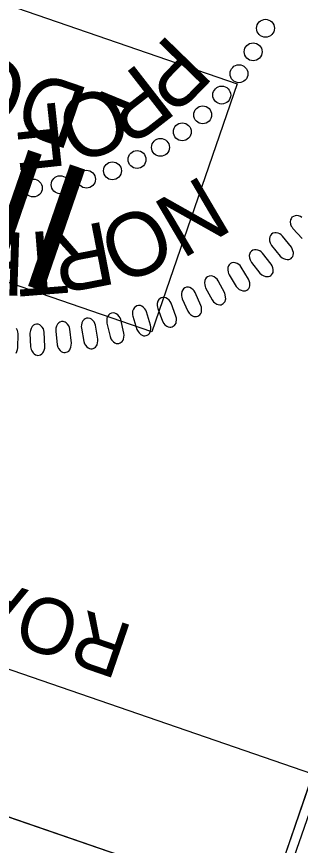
# Model space of a CAD drawing. Extents: x 479650 to 481768, y 492454 to 494037.
# Drawn here: x 479848.6 to 479874, y 492981.7 to 493055.9 of the extents above; entities that cross this region are included whole.
import ezdxf

# ---------------------------------------------------------------- set-up
doc = ezdxf.new("R2010")
doc.units = 0
for name, color, linetype in [('Sheet Clip Boundary CELL', 7, 'Continuous'), ('Sheet PE Seal Cell', 7, 'Continuous'), ('Sheet Plan CELL', 7, 'Continuous'), ('Sheet Sticker Incomplete CELL', 7, 'Continuous')]:
    doc.layers.add(name, color=color, linetype=linetype)

msp = doc.modelspace()

# ---------------------------------------------------------------- linework, layer by layer
at = {"layer": 'Sheet Clip Boundary CELL'}
msp.add_lwpolyline([(480865.415, 492806.897), (480865.415, 492806.897), (481216.518, 493064.432), (481296.644, 493123.205), (481433.971, 493521.819), (480177.877, 493954.834), (480146.865, 493864.823), (480073.721, 493890.25), (479959.678, 493732.811), (479819.951, 493331.117), (479813.597, 493153.331), (479920.245, 493116.586), (479863.719, 492952.486), (480677.398, 492672.068), (480745.444, 492725.051)], close=True, dxfattribs=at)
at = {"layer": 'Sheet PE Seal Cell'}
for points in [[(479874.125, 493037.924), (479873.998, 493037.997), (479873.825, 493038.055), (479873.648, 493038.084), (479873.522, 493038.077), (479873.365, 493038.016), (479873.241, 493037.93), (479873.158, 493037.801), (479873.113, 493037.694), (479873.086, 493037.534), (479873.111, 493037.329), (479873.182, 493037.15), (479873.247, 493037.034), (479873.323, 493036.928), (479874.146, 493036.019)], [(479848.528, 493025.754), (479848.598, 493025.902), (479848.661, 493026.081), (479848.686, 493026.24), (479848.716, 493027.496), (479848.697, 493027.666), (479848.654, 493027.806), (479848.568, 493027.968)]]:
    msp.add_lwpolyline(points, dxfattribs=at)
for points in [[(479871.423, 493035.415), (479872.188, 493034.456), (479872.353, 493034.308), (479872.481, 493034.231), (479872.675, 493034.168), (479872.819, 493034.143), (479872.957, 493034.151), (479873.063, 493034.185), (479873.164, 493034.24), (479873.239, 493034.325), (479873.313, 493034.423), (479873.358, 493034.535), (479873.378, 493034.678), (479873.375, 493034.778), (479873.334, 493034.937), (479873.269, 493035.114), (479873.187, 493035.253), (479872.409, 493036.24), (479872.286, 493036.359), (479872.164, 493036.44), (479871.994, 493036.509), (479871.82, 493036.548), (479871.694, 493036.55), (479871.534, 493036.499), (479871.405, 493036.421), (479871.313, 493036.297), (479871.262, 493036.193), (479871.224, 493036.035), (479871.237, 493035.829), (479871.296, 493035.646), (479871.354, 493035.526)], [(479869.616, 493033.898), (479870.373, 493032.933), (479870.538, 493032.784), (479870.665, 493032.706), (479870.858, 493032.642), (479871.002, 493032.616), (479871.139, 493032.622), (479871.246, 493032.655), (479871.347, 493032.709), (479871.423, 493032.794), (479871.498, 493032.892), (479871.544, 493033.003), (479871.565, 493033.146), (479871.563, 493033.246), (479871.523, 493033.405), (479871.459, 493033.584), (479871.379, 493033.722), (479870.609, 493034.716), (479870.486, 493034.835), (479870.365, 493034.917), (479870.196, 493034.988), (479870.022, 493035.028), (479869.896, 493035.03), (479869.735, 493034.981), (479869.606, 493034.904), (479869.512, 493034.781), (479869.461, 493034.677), (479869.422, 493034.52), (479869.433, 493034.313), (479869.491, 493034.13), (479869.548, 493034.01)], [(479867.62, 493032.786), (479868.258, 493031.738), (479868.405, 493031.571), (479868.522, 493031.478), (479868.706, 493031.392), (479868.846, 493031.349), (479868.983, 493031.339), (479869.093, 493031.36), (479869.199, 493031.401), (479869.285, 493031.476), (479869.371, 493031.565), (479869.43, 493031.669), (479869.467, 493031.809), (479869.477, 493031.909), (479869.456, 493032.071), (479869.414, 493032.256), (479869.35, 493032.404), (479868.702, 493033.48), (479868.595, 493033.614), (479868.484, 493033.709), (479868.324, 493033.799), (479868.156, 493033.86), (479868.031, 493033.877), (479867.866, 493033.846), (479867.728, 493033.786), (479867.621, 493033.674), (479867.558, 493033.577), (479867.501, 493033.426), (479867.487, 493033.219), (479867.523, 493033.03), (479867.565, 493032.904)], [(479865.512, 493031.622), (479866.084, 493030.537), (479866.219, 493030.36), (479866.33, 493030.261), (479866.509, 493030.162), (479866.646, 493030.111), (479866.782, 493030.092), (479866.893, 493030.106), (479867.002, 493030.141), (479867.092, 493030.21), (479867.184, 493030.293), (479867.248, 493030.394), (479867.295, 493030.531), (479867.31, 493030.63), (479867.301, 493030.794), (479867.27, 493030.98), (479867.216, 493031.132), (479866.636, 493032.247), (479866.537, 493032.387), (479866.433, 493032.49), (479866.279, 493032.589), (479866.115, 493032.66), (479865.992, 493032.686), (479865.825, 493032.665), (479865.683, 493032.613), (479865.57, 493032.508), (479865.5, 493032.416), (479865.434, 493032.268), (479865.407, 493032.062), (479865.431, 493031.872), (479865.465, 493031.744)], [(479863.417, 493030.642), (479863.919, 493029.523), (479864.043, 493029.337), (479864.148, 493029.231), (479864.32, 493029.123), (479864.452, 493029.062), (479864.588, 493029.035), (479864.7, 493029.042), (479864.81, 493029.07), (479864.904, 493029.134), (479865.001, 493029.211), (479865.072, 493029.307), (479865.127, 493029.442), (479865.149, 493029.539), (479865.149, 493029.703), (479865.13, 493029.891), (479865.085, 493030.045), (479864.577, 493031.195), (479864.488, 493031.341), (479864.389, 493031.449), (479864.242, 493031.558), (479864.082, 493031.641), (479863.961, 493031.674), (479863.794, 493031.664), (479863.649, 493031.62), (479863.529, 493031.522), (479863.454, 493031.434), (479863.378, 493031.292), (479863.339, 493031.088), (479863.351, 493030.896), (479863.377, 493030.766)], [(479861.225, 493029.769), (479861.656, 493028.62), (479861.768, 493028.429), (479861.866, 493028.316), (479862.031, 493028.197), (479862.16, 493028.128), (479862.293, 493028.092), (479862.405, 493028.092), (479862.517, 493028.113), (479862.616, 493028.171), (479862.716, 493028.241), (479862.794, 493028.333), (479862.857, 493028.464), (479862.885, 493028.56), (479862.895, 493028.724), (479862.888, 493028.912), (479862.853, 493029.07), (479862.419, 493030.249), (479862.338, 493030.4), (479862.247, 493030.515), (479862.107, 493030.632), (479861.953, 493030.724), (479861.834, 493030.765), (479861.666, 493030.765), (479861.519, 493030.731), (479861.393, 493030.641), (479861.312, 493030.558), (479861.228, 493030.42), (479861.176, 493030.219), (479861.176, 493030.028), (479861.194, 493029.896)], [(479858.995, 493029.068), (479859.353, 493027.895), (479859.453, 493027.696), (479859.543, 493027.578), (479859.7, 493027.448), (479859.825, 493027.372), (479859.955, 493027.328), (479860.068, 493027.32), (479860.18, 493027.334), (479860.282, 493027.386), (479860.387, 493027.449), (479860.47, 493027.537), (479860.541, 493027.663), (479860.575, 493027.757), (479860.596, 493027.92), (479860.601, 493028.109), (479860.575, 493028.268), (479860.216, 493029.472), (479860.144, 493029.628), (479860.061, 493029.749), (479859.929, 493029.875), (479859.781, 493029.975), (479859.665, 493030.024), (479859.497, 493030.035), (479859.348, 493030.01), (479859.217, 493029.928), (479859.132, 493029.85), (479859.039, 493029.718), (479858.974, 493029.521), (479858.962, 493029.329), (479858.971, 493029.196)], [(479854.383, 493028.017), (479854.591, 493026.808), (479854.665, 493026.597), (479854.74, 493026.469), (479854.879, 493026.321), (479854.993, 493026.229), (479855.117, 493026.17), (479855.227, 493026.148), (479855.341, 493026.148), (479855.448, 493026.186), (479855.561, 493026.236), (479855.654, 493026.313), (479855.74, 493026.429), (479855.786, 493026.518), (479855.827, 493026.676), (479855.855, 493026.864), (479855.85, 493027.025), (479855.644, 493028.264), (479855.594, 493028.427), (479855.525, 493028.557), (479855.411, 493028.699), (479855.276, 493028.818), (479855.167, 493028.88), (479855.002, 493028.913), (479854.851, 493028.907), (479854.711, 493028.842), (479854.616, 493028.775), (479854.507, 493028.655), (479854.419, 493028.468), (479854.382, 493028.28), (479854.375, 493028.147)], [(479856.662, 493028.439), (479856.946, 493027.246), (479857.033, 493027.041), (479857.116, 493026.917), (479857.264, 493026.778), (479857.384, 493026.694), (479857.511, 493026.642), (479857.622, 493026.628), (479857.736, 493026.634), (479857.841, 493026.679), (479857.95, 493026.736), (479858.038, 493026.818), (479858.117, 493026.94), (479858.157, 493027.031), (479858.188, 493027.192), (479858.204, 493027.381), (479858.189, 493027.542), (479857.906, 493028.766), (479857.845, 493028.925), (479857.769, 493029.051), (479857.644, 493029.185), (479857.503, 493029.295), (479857.391, 493029.351), (479857.224, 493029.372), (479857.074, 493029.357), (479856.937, 493029.284), (479856.847, 493029.211), (479856.746, 493029.085), (479856.67, 493028.892), (479856.646, 493028.701), (479856.646, 493028.569)], [(479849.777, 493027.545), (479849.832, 493026.319), (479849.879, 493026.101), (479849.937, 493025.964), (479850.057, 493025.8), (479850.159, 493025.694), (479850.275, 493025.62), (479850.381, 493025.585), (479850.494, 493025.57), (479850.605, 493025.595), (479850.724, 493025.63), (479850.825, 493025.695), (479850.926, 493025.799), (479850.981, 493025.881), (479851.042, 493026.034), (479851.094, 493026.216), (479851.109, 493026.376), (479851.06, 493027.632), (479851.03, 493027.8), (479850.979, 493027.938), (479850.882, 493028.093), (479850.764, 493028.227), (479850.664, 493028.303), (479850.504, 493028.356), (479850.353, 493028.369), (479850.206, 493028.322), (479850.104, 493028.268), (479849.981, 493028.162), (479849.869, 493027.988), (479849.81, 493027.805), (479849.786, 493027.675)], [(479852.083, 493027.737), (479852.214, 493026.517), (479852.275, 493026.303), (479852.343, 493026.17), (479852.472, 493026.013), (479852.581, 493025.915), (479852.701, 493025.847), (479852.809, 493025.819), (479852.922, 493025.811), (479853.032, 493025.843), (479853.147, 493025.885), (479853.245, 493025.956), (479853.339, 493026.067), (479853.389, 493026.152), (479853.44, 493026.308), (479853.48, 493026.493), (479853.486, 493026.654), (479853.357, 493027.904), (479853.317, 493028.071), (479853.257, 493028.205), (479853.151, 493028.353), (479853.024, 493028.481), (479852.92, 493028.549), (479852.757, 493028.592), (479852.606, 493028.596), (479852.462, 493028.54), (479852.363, 493028.479), (479852.248, 493028.366), (479852.147, 493028.185), (479852.099, 493027.999), (479852.083, 493027.867)]]:
    msp.add_lwpolyline(points, close=True, dxfattribs=at)
for centre in [(479870.87, 493054.858), (479869.765, 493052.753), (479868.498, 493050.788), (479866.954, 493048.877), (479865.248, 493047.105), (479863.419, 493045.587), (479861.465, 493044.196), (479859.364, 493043.109), (479857.162, 493042.098), (479852.477, 493040.848), (479854.837, 493041.341), (479850.076, 493040.554)]:
    msp.add_circle(centre, 0.801, dxfattribs=at)
at = {"layer": 'Sheet Plan CELL'}
for q in [(479681.911, 493041.391), (479681.911, 493041.391), (479875.114, 492988.059)]:
    msp.add_line((479871.047, 492976.253), q, dxfattribs=at)
for points in [[(481433.971, 493521.819), (481091.969, 492529.104), (479862.874, 492952.534), (479911.745, 493094.415), (479722.622, 493159.589), (480015.773, 494010.441)], [(479875.114, 492988.059), (479780.521, 493020.65), (479817.172, 493127.026), (479911.745, 493094.415)], [(479862.874, 492952.534), (479673.716, 493017.719), (479681.911, 493041.391), (479871.047, 492976.253)]]:
    msp.add_lwpolyline(points, close=True, dxfattribs=at)
at = {"layer": 'Sheet Sticker Incomplete CELL'}
msp.add_lwpolyline([(479868.336, 493049.89), (479860.681, 493027.672), (479721.698, 493075.556), (479729.353, 493097.774)], close=True, dxfattribs=at)

# ---------------------------------------------------------------- texts
at = {"layer": 'Sheet PE Seal Cell'}
for s, rotation, p in [('P', 225.79665, (479862.285, 493054.494)), ('R', 217.85685, (479859.595, 493051.865)), ('O', 201.97726, (479857.146, 493050.016)), ('F', 186.09766, (479852.628, 493048.253)), ('N', 210.49177, (479865.241, 493041.797)), ('O', 204.00241, (479860.853, 493039.337)), ('R', 191.0237, (479856.581, 493037.605)), ('H', 178.04499, (479849.446, 493036.543)), ('T', 184.53434, (479852.911, 493036.841))]:
    msp.add_text(s, height=5.669, rotation=rotation, dxfattribs=at).set_placement(p)
at = {"layer": 'Sheet Plan CELL'}
msp.add_text('ROADWAY DESIGN', height=5.0001, rotation=160.98924, dxfattribs=at).set_placement((479859.174, 493001.272))
at = {"layer": 'Sheet Sticker Incomplete CELL'}
for s, height, p in [('DO NOT USE FOR R/W ACQUISITION', 5.76, (479855.254, 493049.373)), ('INCOMPLETE PLANS', 11.52, (479856.063, 493041.743))]:
    msp.add_text(s, height=height, rotation=160.98924, dxfattribs=at).set_placement(p)

doc.saveas('drawing.dxf')
